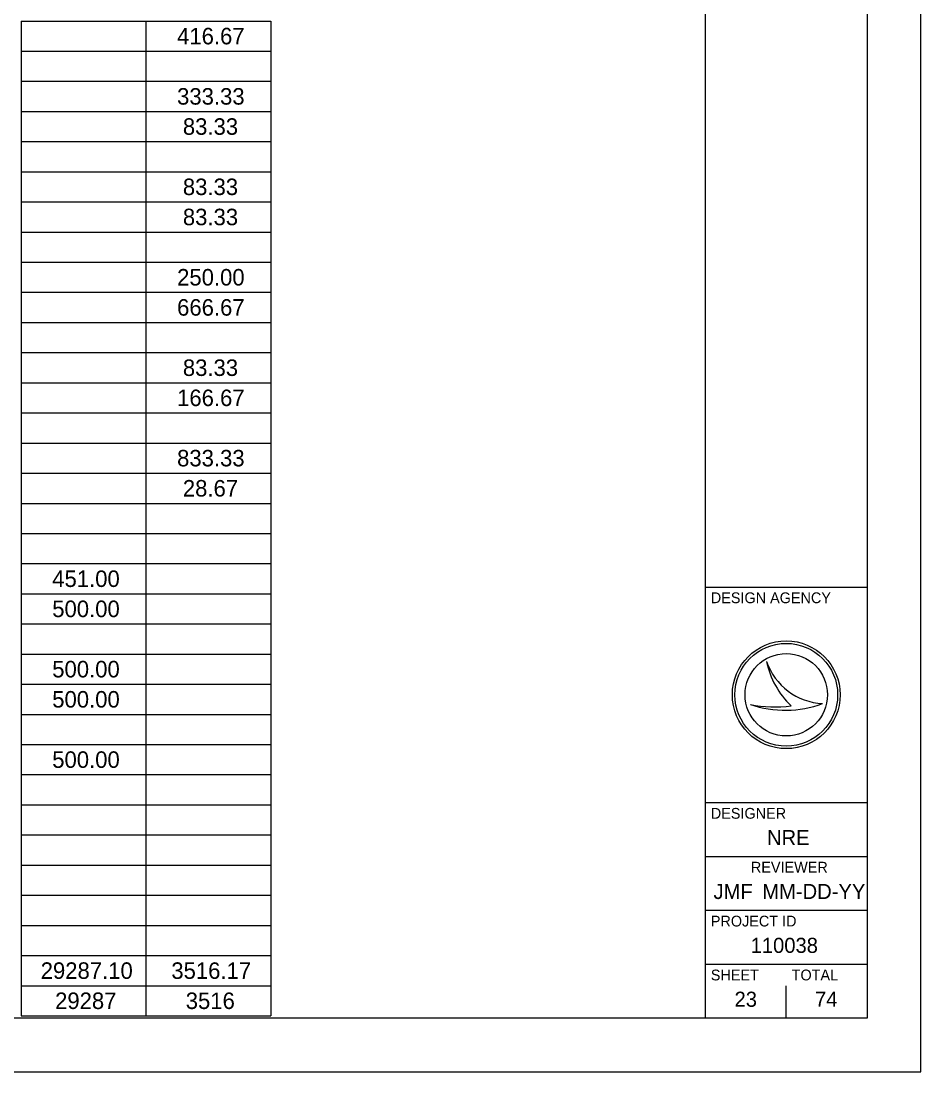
# Model space of a CAD drawing. Extents: x 0 to 34.4, y 0 to 47.
# Drawn here: x 25.65 to 34, y 0 to 9.75 of the extents above; entities that cross this region are included whole.
import ezdxf

# ---------------------------------------------------------------- set-up
doc = ezdxf.new("R2010")
doc.units = 0
for name, color, linetype in [('SH_Border', 7, 'Continuous'), ('SH_Cut_Line', 7, 'Continuous'), ('SH_Data', 7, 'Continuous'), ('SH_Text', 7, 'Continuous')]:
    doc.layers.add(name, color=color, linetype=linetype)

msp = doc.modelspace()

# ---------------------------------------------------------------- linework, layer by layer
at = {"layer": 'SH_Border'}
for p, q in [((32, 0.5), (32, 21.5)), ((32, 4.5), (33.5, 4.5)), ((32, 2.5), (33.5, 2.5)), ((32, 2), (33.5, 2)), ((32, 1.5), (33.5, 1.5)), ((32, 1), (33.5, 1))]:
    msp.add_line(p, q, dxfattribs=at)
msp.add_lwpolyline([(1.5, 21.5), (33.5, 21.5), (33.5, 0.5), (1.5, 0.5)], close=True, dxfattribs=at)
at = {"layer": 'SH_Cut_Line'}
msp.add_lwpolyline([(0, 0), (34, 0), (34, 22), (0, 22)], close=True, dxfattribs=at)
at = {"layer": 'SH_Data'}
for p, q in [((32.5674, 3.8096), (32.5675, 3.8096)), ((32.75, 3.5), (32.75, 3.5)), ((33.0873, 3.4185), (33.0873, 3.4185)), ((32.4172, 3.4095), (32.4172, 3.4095)), ((32.75, 0.5), (32.75, 0.8)), ((32.375, 0.675), (32.375, 0.675))]:
    msp.add_line(p, q, dxfattribs=at)
for radius in [0.5, 0.4768, 0.4768, 0.3822]:
    msp.add_circle((32.75, 3.5), radius, dxfattribs=at)
for centre, radius, start, end in [((33.1159, 3.9976), 0.5798, 198.92567, 198.93195), ((33.3467, 3.9701), 0.7956, 191.63793, 191.64215), ((33.1159, 3.9976), 0.5798, 198.93195, 267.16574), ((33.3467, 3.9701), 0.7956, 191.64215, 226.09467), ((32.7394, 4.37), 1.0131, 251.45764, 290.08324), ((32.648, 4.6543), 1.2661, 259.49639, 259.49952), ((32.7394, 4.37), 1.0131, 251.45274, 251.45764), ((32.648, 4.6543), 1.2661, 259.49952, 276.66723)]:
    msp.add_arc(centre, radius, start, end, dxfattribs=at)
at = {"layer": 'SH_Text'}
for p, q in [((25.6492, 9.7518), (27.9668, 9.7518)), ((25.6492, 9.7518), (25.6492, 9.472)), ((26.808, 9.7518), (26.808, 9.472)), ((27.9668, 9.7518), (27.9668, 9.472)), ((25.6492, 9.472), (27.9668, 9.472)), ((25.6492, 9.472), (25.6492, 9.1923)), ((26.808, 9.472), (26.808, 9.1923)), ((27.9668, 9.472), (27.9668, 9.1923)), ((25.6492, 9.1923), (27.9668, 9.1923)), ((25.6492, 9.1923), (25.6492, 8.9126)), ((26.808, 9.1923), (26.808, 8.9126)), ((27.9668, 9.1923), (27.9668, 8.9126)), ((25.6492, 8.9126), (27.9668, 8.9126)), ((25.6492, 8.9126), (25.6492, 8.6329)), ((26.808, 8.9126), (26.808, 8.6329)), ((27.9668, 8.9126), (27.9668, 8.6329)), ((25.6492, 8.6329), (27.9668, 8.6329)), ((25.6492, 8.6329), (25.6492, 8.3532)), ((26.808, 8.6329), (26.808, 8.3532)), ((27.9668, 8.6329), (27.9668, 8.3532)), ((25.6492, 8.3532), (27.9668, 8.3532)), ((25.6492, 8.3532), (25.6492, 8.0734)), ((26.808, 8.3532), (26.808, 8.0734)), ((27.9668, 8.3532), (27.9668, 8.0734)), ((25.6492, 8.0734), (27.9668, 8.0734)), ((25.6492, 8.0734), (25.6492, 7.7937)), ((26.808, 8.0734), (26.808, 7.7937)), ((27.9668, 8.0734), (27.9668, 7.7937)), ((25.6492, 7.7937), (27.9668, 7.7937)), ((25.6492, 7.7937), (25.6492, 7.514)), ((26.808, 7.7937), (26.808, 7.514)), ((27.9668, 7.7937), (27.9668, 7.514)), ((25.6492, 7.514), (27.9668, 7.514)), ((25.6492, 7.514), (25.6492, 7.2343)), ((26.808, 7.514), (26.808, 7.2343)), ((27.9668, 7.514), (27.9668, 7.2343)), ((25.6492, 7.2343), (27.9668, 7.2343)), ((25.6492, 7.2343), (25.6492, 6.9546)), ((26.808, 7.2343), (26.808, 6.9546)), ((27.9668, 7.2343), (27.9668, 6.9546)), ((25.6492, 6.9546), (27.9668, 6.9546)), ((25.6492, 6.9546), (25.6492, 6.6748)), ((26.808, 6.9546), (26.808, 6.6748)), ((27.9668, 6.9546), (27.9668, 6.6748)), ((25.6492, 6.6748), (27.9668, 6.6748)), ((25.6492, 6.6748), (25.6492, 6.3951)), ((26.808, 6.6748), (26.808, 6.3951)), ((27.9668, 6.6748), (27.9668, 6.3951)), ((25.6492, 6.3951), (27.9668, 6.3951)), ((25.6492, 6.3951), (25.6492, 6.1154)), ((26.808, 6.3951), (26.808, 6.1154)), ((27.9668, 6.3951), (27.9668, 6.1154)), ((25.6492, 6.1154), (27.9668, 6.1154)), ((25.6492, 6.1154), (25.6492, 5.8357)), ((26.808, 6.1154), (26.808, 5.8357)), ((27.9668, 6.1154), (27.9668, 5.8357)), ((25.6492, 5.8357), (27.9668, 5.8357)), ((25.6492, 5.8357), (25.6492, 5.556)), ((26.808, 5.8357), (26.808, 5.556)), ((27.9668, 5.8357), (27.9668, 5.556)), ((25.6492, 5.556), (27.9668, 5.556)), ((25.6492, 5.556), (25.6492, 4.9965)), ((26.808, 5.556), (26.808, 4.9965)), ((27.9668, 5.556), (27.9668, 4.9965)), ((25.6492, 5.2762), (27.9668, 5.2762)), ((25.6492, 4.9965), (27.9668, 4.9965)), ((25.6492, 4.9965), (25.6492, 4.7168)), ((26.808, 4.9965), (26.808, 4.7168)), ((27.9668, 4.9965), (27.9668, 4.7168)), ((25.6492, 4.7168), (27.9668, 4.7168)), ((25.6492, 4.7168), (25.6492, 4.4371)), ((26.808, 4.7168), (26.808, 4.4371)), ((27.9668, 4.7168), (27.9668, 4.4371)), ((25.6492, 4.4371), (27.9668, 4.4371)), ((25.6492, 4.4371), (25.6492, 4.1574)), ((26.808, 4.4371), (26.808, 4.1574)), ((27.9668, 4.4371), (27.9668, 4.1574)), ((25.6492, 4.1574), (27.9668, 4.1574)), ((25.6492, 4.1574), (25.6492, 3.5979)), ((26.808, 4.1574), (26.808, 3.5979)), ((27.9668, 4.1574), (27.9668, 3.5979)), ((25.6492, 3.8776), (27.9668, 3.8776)), ((25.6492, 3.5979), (27.9668, 3.5979)), ((25.6492, 3.5979), (25.6492, 3.3182)), ((26.808, 3.5979), (26.808, 3.3182)), ((27.9668, 3.5979), (27.9668, 3.3182)), ((25.6492, 3.3182), (27.9668, 3.3182)), ((25.6492, 3.3182), (25.6492, 3.0385)), ((26.808, 3.3182), (26.808, 3.0385)), ((27.9668, 3.3182), (27.9668, 3.0385)), ((25.6492, 3.0385), (27.9668, 3.0385)), ((25.6492, 3.0385), (25.6492, 2.7588)), ((26.808, 3.0385), (26.808, 2.7588)), ((27.9668, 3.0385), (27.9668, 2.7588)), ((25.6492, 2.7588), (27.9668, 2.7588)), ((25.6492, 2.7588), (25.6492, 2.1993)), ((26.808, 2.7588), (26.808, 2.1993)), ((27.9668, 2.7588), (27.9668, 2.1993)), ((25.6492, 2.479), (27.9668, 2.479)), ((25.6492, 2.1993), (27.9668, 2.1993)), ((25.6492, 2.1993), (25.6492, 1.9196)), ((26.808, 2.1993), (26.808, 1.9196)), ((27.9668, 2.1993), (27.9668, 1.9196)), ((25.6492, 1.9196), (27.9668, 1.9196)), ((25.6492, 1.9196), (25.6492, 1.6399)), ((26.808, 1.9196), (26.808, 1.6399)), ((27.9668, 1.9196), (27.9668, 1.6399)), ((25.6492, 1.6399), (27.9668, 1.6399)), ((25.6492, 1.6399), (25.6492, 1.3602)), ((26.808, 1.6399), (26.808, 1.3602)), ((27.9668, 1.6399), (27.9668, 1.3602)), ((25.6492, 1.3602), (27.9668, 1.3602)), ((25.6492, 1.3602), (25.6492, 0.8007)), ((26.808, 1.3602), (26.808, 0.8007)), ((27.9668, 1.3602), (27.9668, 0.8007)), ((25.6492, 1.0804), (27.9668, 1.0804)), ((25.6492, 0.8007), (27.9668, 0.8007)), ((25.6492, 0.8007), (25.6492, 0.521)), ((26.808, 0.8007), (26.808, 0.521)), ((27.9668, 0.8007), (27.9668, 0.521)), ((25.6492, 0.521), (27.9668, 0.521))]:
    msp.add_line(p, q, dxfattribs=at)

# ---------------------------------------------------------------- texts
at = {"layer": 'SH_Data'}
for s, height, p in [('DESIGN AGENCY', 0.1, (32.05, 4.35)), ('DESIGNER', 0.1, (32.05, 2.35)), ('NRE', 0.14, (32.5709, 2.105)), ('REVIEWER', 0.1, (32.4218, 1.85)), ('JMF', 0.14, (32.0746, 1.605)), ('MM-DD-YY', 0.14, (32.5273, 1.605)), ('PROJECT ID', 0.1, (32.05, 1.35)), ('110038', 0.14, (32.4193, 1.105)), ('SHEET', 0.1, (32.05, 0.85)), ('TOTAL', 0.1, (32.8, 0.85)), ('23', 0.14, (32.27, 0.605)), ('74', 0.14, (33.0164, 0.605))]:
    msp.add_text(s, height=height, dxfattribs=at).set_placement(p)
at = {"layer": 'SH_Text'}
for s, p in [('416.67', (27.0974, 9.5353)), ('333.33', (27.0974, 8.9759)), ('83.33', (27.1509, 8.6961)), ('83.33', (27.1509, 8.1367)), ('83.33', (27.1509, 7.857)), ('250.00', (27.0976, 7.2976)), ('666.67', (27.0974, 7.0178)), ('83.33', (27.1509, 6.4584)), ('166.67', (27.0974, 6.1787)), ('833.33', (27.0974, 5.6192)), ('28.67', (27.1509, 5.3395)), ('451.00', (25.9388, 4.5003)), ('500.00', (25.9388, 4.2206)), ('500.00', (25.9388, 3.6612)), ('500.00', (25.9388, 3.3815)), ('500.00', (25.9388, 2.822)), ('29287.10', (25.8317, 0.864)), ('3516.17', (27.0438, 0.864)), ('29287', (25.9653, 0.5843)), ('3516', (27.1776, 0.5843))]:
    msp.add_text(s, height=0.15318, dxfattribs=at).set_placement(p)

doc.saveas('drawing.dxf')
